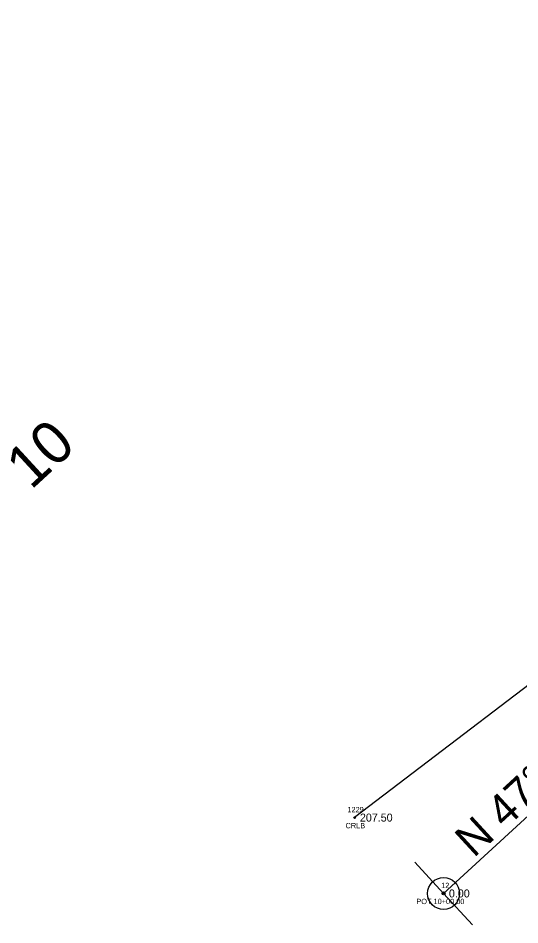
# Model space of a CAD drawing. Extents: x 2259948 to 2261336, y 1064647 to 1065986.
# Drawn here: x 2260425 to 2260519.2, y 1064662.3 to 1064832.3 of the extents above; entities that cross this region are included whole.
import ezdxf

# ---------------------------------------------------------------- set-up
doc = ezdxf.new("R2010")
doc.units = 0
for name, color, linetype in [('RD_EX_H2O', 7, 'Continuous'), ('RD_EX_H2O_txCode', 7, 'Continuous'), ('RD_EX_TX_H2O_ELEV', 7, 'Continuous'), ('RD_HC_Cl', 7, 'Continuous'), ('RD_HC_Data', 7, 'Continuous'), ('RD_HC_Data_Tic', 7, 'Continuous'), ('RD_HC_Survey_ELEV', 7, 'Continuous'), ('RD_HC_TX_Sta50', 7, 'Continuous'), ('RD_HC_txCode', 7, 'Continuous'), ('RD_SMD_Locator', 7, 'Continuous')]:
    doc.layers.add(name, color=color, linetype=linetype)

msp = doc.modelspace()

# ---------------------------------------------------------------- linework, layer by layer
at = {"layer": 'RD_EX_H2O'}
msp.add_lwpolyline([(2260766.96, 1065089.79), (2260769.94, 1065084.22), (2260769.59, 1065075.21), (2260766.59, 1065063.56), (2260718.2, 1065001.51), (2260666.03, 1064928.94), (2260617.31, 1064851.47), (2260573.34, 1064761.94), (2260536.11, 1064718.88), (2260488.15, 1064682.39)], dxfattribs=at)
at = {"layer": 'RD_HC_Cl'}
msp.add_line((2260504.85, 1064668.17), (2260558.67, 1064717.71), dxfattribs=at)
at = {"layer": 'RD_HC_Data'}
for radius in [3, 0.282]:
    msp.add_circle((2260504.85, 1064668.17), radius, dxfattribs=at)
at = {"layer": 'RD_HC_Data_Tic'}
for q in [(2260499.43, 1064674.05), (2260510.26, 1064662.28)]:
    msp.add_line((2260504.85, 1064668.17), q, dxfattribs=at)
at = {"layer": 'RD_SMD_Locator'}
for centre in [(2260488.15, 1064682.39), (2260504.85, 1064668.17)]:
    msp.add_circle(centre, 0.15, dxfattribs=at)

# ---------------------------------------------------------------- texts
at = {"layer": 'RD_EX_H2O_txCode'}
for s, p in [('1229', (2260486.8, 1064683.39)), ('CRLB', (2260486.45, 1064680.39))]:
    msp.add_text(s, height=1, dxfattribs=at).set_placement(p)
at = {"layer": 'RD_EX_TX_H2O_ELEV'}
msp.add_text('207.50', height=1.5, dxfattribs=at).set_placement((2260489.15, 1064681.64))
at = {"layer": 'RD_HC_Data'}
msp.add_text('N 47%%d 22\' 04" E', height=6, rotation=42.6323, dxfattribs=at).set_placement((2260510.5, 1064674.73))
at = {"layer": 'RD_HC_Survey_ELEV'}
msp.add_text('0.00', height=1.5, dxfattribs=at).set_placement((2260505.85, 1064667.42))
at = {"layer": 'RD_HC_TX_Sta50'}
msp.add_text('10', height=8, rotation=42.6323, dxfattribs=at).set_placement((2260427.43, 1064743.7))
at = {"layer": 'RD_HC_txCode'}
for s, p in [('12', (2260504.4, 1064669.17)), ('POT 10+00.00', (2260499.74, 1064666.17))]:
    msp.add_text(s, height=1, dxfattribs=at).set_placement(p)

doc.saveas('drawing.dxf')
